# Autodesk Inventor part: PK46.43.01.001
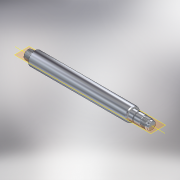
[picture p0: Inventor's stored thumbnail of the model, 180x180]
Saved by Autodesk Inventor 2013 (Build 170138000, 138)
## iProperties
Shininess: 64.0
Length Units: 11269
Angle Units: 11279
Time Units: 11290
Mass Units: 11283
Length Display Precision: 3
Angle Display Precision: 2
Compacted: True
Part Number: PK46.43.01.001
Document SubType Name: Modeling
Created: 2004-11
Material: Сталь высокопрочная низколегированная
Designer: ELarisa
Manufacturer: Standard
Standards Organization: Custom
Density: 7.84 g/cm^3
Density: 0.0
Volumn: 0.0
Area: 0.0
PropertySet Name: Model Information
Control State: 0
Master: False
Checked Out: False
Checked Out Date: 2008-10-15
Last Check In Date: 2008-10-15
Author: ELarisa
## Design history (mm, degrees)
revolve "Вращение1" stored, may be unused: angle "d24" = 90 deg
chamfer "Фаска1" distance "d25" = 2; stored, may be unused: second distance "d26" = 2, angle "d59" = 45 deg
fillet "Сопряжение1" dims "d29" = 1.6
fillet "Сопряжение2" dims "d30" = 0.5
chamfer "Фаска2" distance "d31" = 1.5; stored, may be unused: second distance "d32" = 2, angle "d60" = 45 deg
fillet "Сопряжение3" dims "d33" = 0.5
fillet "Сопряжение4" dims "d34" = 1.6
fillet "Сопряжение5" dims "d35" = 0.6
fillet "Сопряжение6" dims "d36" = 0.2
node "РабОсь1"
sketch "Эскиз2"
  geometry: L1 (582, 14)-(532, 14); L2 (527, 28.683)-(527, 16.683); L3 (570, -21)-(570, 21) reference; L4 (549.5, -21)-(549.5, 21) reference; L5 (570, -21)-(570, 21) reference; L6 (-116.4, 0)-(698.4, 0) reference; L7 (582, 16.5)-(582, -16.5) reference; L8 (527, 28.683)-(582, 24); L9 (582, 24)-(582, 14); A1 r 6 centre (532, 20) between (527, 16.683) and (532, 14)
  constraints: 8 end point, 2 point on circle, 1 centre point, 1 collinear, 1 horizontal, 1 perpendicular
  dimensions: "d37" = 14 distance between parallel lines of L1 L6; "d38" = 10 distance of L8.end L1.start; "d40" = 50 distance of L1.start L1.end; "d41" = 55 horizontal distance of L2.start L8.end; "d44" = 6 distance from line of L1 A1.centre; "d45" = 12 distance of L2.start L2.end; "d46" = 6 radius of A1; "d47" = 5 distance from line of L2 A1.centre (derived); "d48" = 0 horizontal distance of L7.start L1.start
extrude "Выдавливание1" cut sketch "Эскиз2" stored distance "d49" = 10; taper "d50" = 0 deg
feature "Резьба1" dims "d54" = 10, "d55" = 0
feature "Резьба2" dims "d56" = 10, "d57" = 0
body "Solid1"
sketch "Эскиз1"
  geometry: L1 (0, 0)-(0, 21); L2 (0, 21)-(23.5, 21); L3 (25, 19.5)-(30, 19.5); L4 (33, 31.5)-(487, 31.5); L5 (492, 30.16)-(492, 22); L6 (492, 22)-(512, 22); L7 (512, 22)-(512, 20.15); L8 (512, 20.15)-(516, 20.15); L9 (516, 20.15)-(516, 22); L10 (516, 22)-(543, 22); L11 (543, 22)-(543, 19.5); L12 (543, 19.5)-(548, 19.5); L13 (548, 19.5)-(549.5, 21); L14 (549.5, 21)-(570, 21); L15 (570, 21)-(573, 18); L16 (573, 18)-(582, 18); L17 (582, 18)-(582, 0); L18 (582, 0)-(0, 0); L19 (30, 19.5)-(30, 25.066); L20 (492, 30.16)-(487, 31.5); L21 (30, 25.066)-(33, 31.5); L22 (25, 19.5)-(23.5, 21)
  constraints: 44 end point, 11 perpendicular, 5 parallel, 1 collinear, 1 vertical, 1 other
  dimensions: "d1" = 582 distance of L17.end L1.start; "d2" = 31.5 distance between parallel lines of L18 L4; "d3" = 18 distance between parallel lines of L18 L16; "d4" = 21 distance between parallel lines of L18 L2; "d5" = 19.5 distance between parallel lines of L18 L3; "d7" = 30 distance between parallel lines of L19 L1; "d8" = 9 distance of L15.end L16.end; "d9" = 135 deg angle of L16 L15; "d10" = 90 distance from line of L5.start L17; "d11" = 51 distance between parallel lines of L11 L5; "d12" = 20 horizontal distance of L6.end L5.start; "d13" = 4 distance of L7.end L8.end; "d14" = 5 distance of L11.end L12.end; "d15" = 135 deg angle of L12 L13; "d16" = 22 distance between parallel lines of L18 L6; "d17" = 20.15 distance between parallel lines of L18 L8; "d18" = 21 distance between parallel lines of L18 L14; "d20" = 15 deg angle of L20 L4; "d21" = 5 horizontal distance of L4.end L5.start; "d22" = 65 deg angle of L4 L21; "d23" = 3 horizontal distance of L19.end L4.start; "d27" = 45 deg angle of L22 L2; "d28" = 5 distance of L3.start L3.end; "d58" = 19.5 distance between parallel lines of L18 L12
node "Спроецированная петля1"
